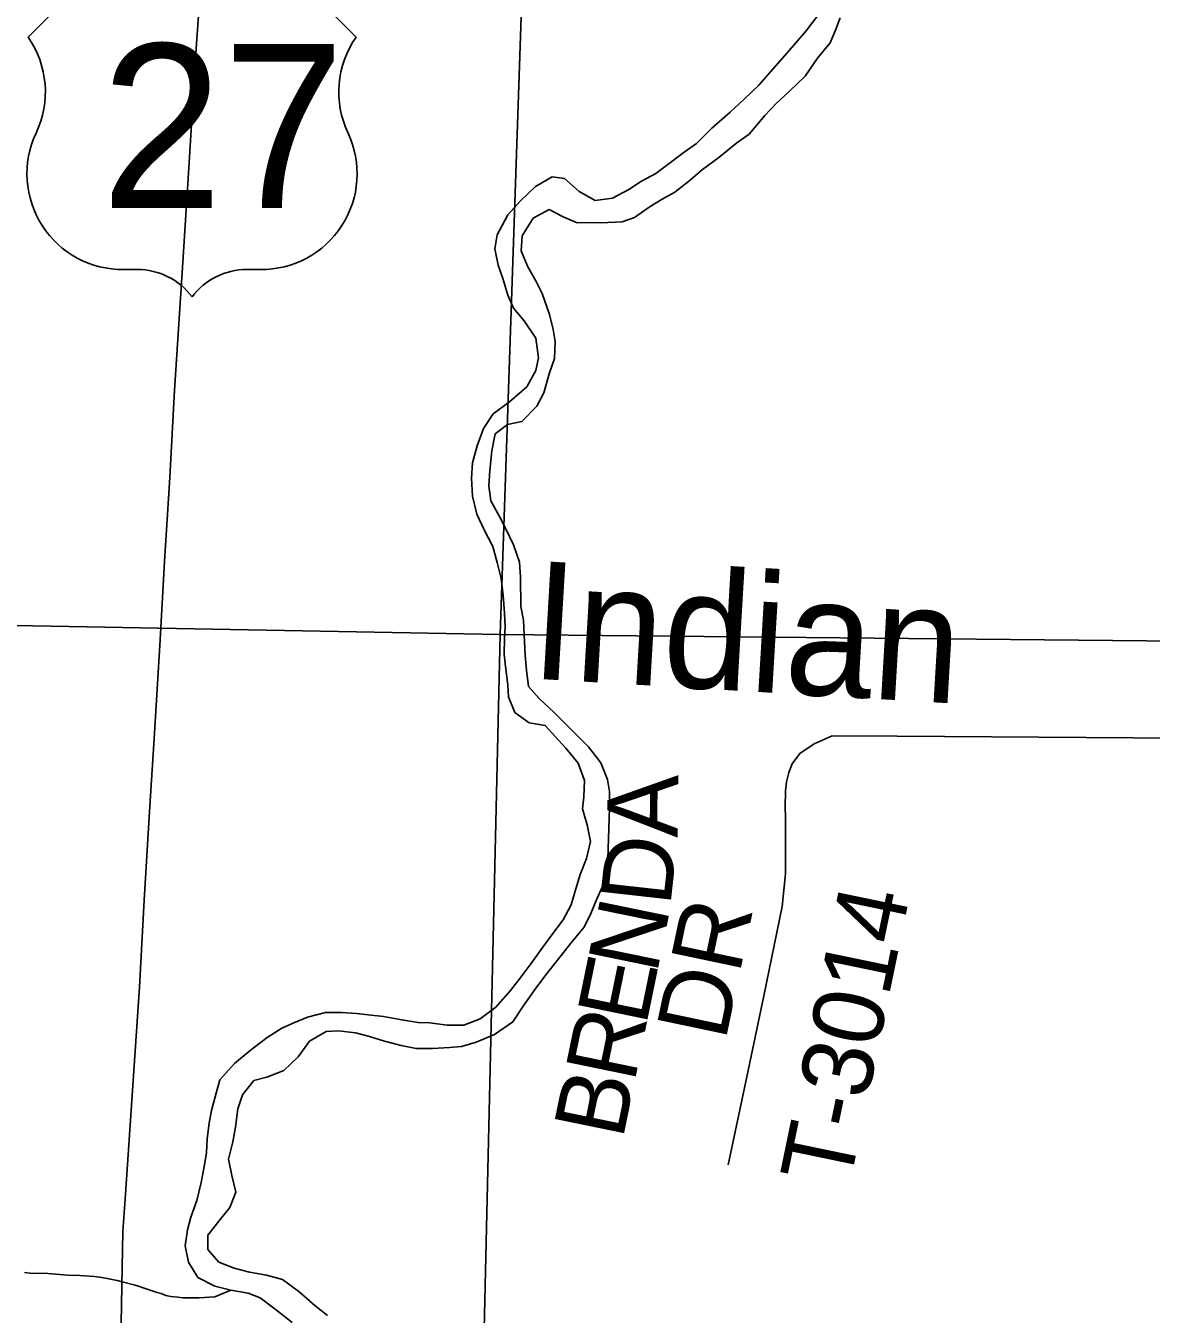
# Model space of a CAD drawing. Extents: x 0 to 34, y -2.3 to 22.
# Drawn here: x 5.006 to 5.911, y 18.814 to 19.85 of the extents above; entities that cross this region are included whole.
import ezdxf

# ---------------------------------------------------------------- set-up
doc = ezdxf.new("R2010")
doc.units = 0
for name, color, linetype in [('GM_X_Major_River', 7, 'Continuous'), ('GM_X_Minor_River', 7, 'Continuous'), ('GM_X_Minor_River_Text', 7, 'Continuous'), ('GM_X_Section', 7, 'Continuous'), ('GM_X_Township_Road', 7, 'Continuous'), ('GM_X_Township_Road_Text', 7, 'Continuous'), ('GM_X_US_Location', 7, 'Continuous'), ('GM_X_US_Route', 7, 'Continuous'), ('GM_X_US_Shield', 7, 'Continuous')]:
    doc.layers.add(name, color=color, linetype=linetype)

msp = doc.modelspace()

# ---------------------------------------------------------------- linework, layer by layer
at = {"layer": 'GM_X_Major_River'}
for p, q in [((5.6435, 19.859), (5.6333, 19.8456)), ((5.6569, 19.8462), (5.6605, 19.856)), ((5.6333, 19.8456), (5.6251, 19.8359)), ((5.6525, 19.8361), (5.6569, 19.8462)), ((5.6251, 19.8359), (5.6142, 19.8236)), ((5.6424, 19.8237), (5.6525, 19.8361)), ((5.6142, 19.8236), (5.6045, 19.8127)), ((5.6326, 19.8091), (5.6424, 19.8237)), ((5.6045, 19.8127), (5.5952, 19.8019)), ((5.6198, 19.7972), (5.6326, 19.8091)), ((5.5952, 19.8019), (5.5835, 19.7908)), ((5.6093, 19.7872), (5.6198, 19.7972)), ((5.5835, 19.7908), (5.5723, 19.7803)), ((5.6, 19.7775), (5.6093, 19.7872)), ((5.5723, 19.7803), (5.5576, 19.7674)), ((5.5875, 19.7626), (5.6, 19.7775)), ((5.5576, 19.7674), (5.5452, 19.7551)), ((5.5775, 19.7555), (5.5875, 19.7626)), ((5.5452, 19.7551), (5.5351, 19.7481)), ((5.5632, 19.7437), (5.5775, 19.7555)), ((5.5351, 19.7481), (5.522, 19.7381)), ((5.55, 19.7341), (5.5632, 19.7437)), ((5.5124, 19.731), (5.5008, 19.7248)), ((5.522, 19.7381), (5.5124, 19.731)), ((5.5388, 19.7244), (5.55, 19.7341)), ((5.4291, 19.7282), (5.4156, 19.7205)), ((5.4389, 19.7269), (5.4291, 19.7282)), ((5.4509, 19.7164), (5.4389, 19.7269)), ((5.5008, 19.7248), (5.4908, 19.7182)), ((5.5276, 19.7159), (5.5388, 19.7244)), ((5.4156, 19.7205), (5.4036, 19.709)), ((5.4636, 19.7093), (5.4509, 19.7164)), ((5.4777, 19.7112), (5.4636, 19.7093)), ((5.4908, 19.7182), (5.4777, 19.7112)), ((5.508, 19.7045), (5.5176, 19.7104)), ((5.5176, 19.7104), (5.5276, 19.7159)), ((5.4036, 19.709), (5.3935, 19.6978)), ((5.4139, 19.6951), (5.4266, 19.702)), ((5.4266, 19.702), (5.4379, 19.6961)), ((5.4953, 19.6957), (5.508, 19.7045)), ((5.3935, 19.6978), (5.3848, 19.6816)), ((5.4049, 19.6808), (5.4139, 19.6951)), ((5.4379, 19.6961), (5.4492, 19.6913)), ((5.4492, 19.6913), (5.4587, 19.6915)), ((5.4587, 19.6915), (5.4682, 19.6913)), ((5.4682, 19.6913), (5.4853, 19.6921)), ((5.4853, 19.6921), (5.4953, 19.6957)), ((5.3848, 19.6816), (5.383, 19.6703)), ((5.4043, 19.6687), (5.4049, 19.6808)), ((5.383, 19.6703), (5.3858, 19.6573)), ((5.4093, 19.6564), (5.4043, 19.6687)), ((5.3858, 19.6573), (5.3894, 19.6466)), ((5.4163, 19.6441), (5.4093, 19.6564)), ((5.3894, 19.6466), (5.3936, 19.6332)), ((5.421, 19.6345), (5.4163, 19.6441)), ((5.3936, 19.6332), (5.398, 19.6228)), ((5.4271, 19.6177), (5.421, 19.6345)), ((5.398, 19.6228), (5.4065, 19.6124)), ((5.4299, 19.6055), (5.4271, 19.6177)), ((5.4065, 19.6124), (5.4161, 19.5985)), ((5.4161, 19.5985), (5.418, 19.5829)), ((5.4316, 19.5959), (5.4299, 19.6055)), ((5.4309, 19.5823), (5.4316, 19.5959)), ((5.418, 19.5829), (5.4159, 19.5727)), ((5.4269, 19.5706), (5.4309, 19.5823)), ((5.4159, 19.5727), (5.4088, 19.5596)), ((5.4224, 19.5547), (5.4269, 19.5706)), ((5.4088, 19.5596), (5.3949, 19.5473)), ((5.3949, 19.5473), (5.3817, 19.5377)), ((5.4168, 19.5438), (5.4224, 19.5547)), ((5.3817, 19.5377), (5.3739, 19.5261)), ((5.4048, 19.5315), (5.4168, 19.5438)), ((5.3739, 19.5261), (5.3687, 19.5121)), ((5.3833, 19.5217), (5.3933, 19.5291)), ((5.3933, 19.5291), (5.4048, 19.5315)), ((5.3807, 19.5081), (5.3833, 19.5217)), ((5.3687, 19.5121), (5.365, 19.4985)), ((5.3789, 19.4922), (5.3807, 19.5081)), ((5.365, 19.4985), (5.3643, 19.486)), ((5.3643, 19.486), (5.3651, 19.4716)), ((5.3782, 19.48), (5.3789, 19.4922)), ((5.3799, 19.4678), (5.3782, 19.48)), ((5.3651, 19.4716), (5.3686, 19.457)), ((5.3868, 19.4552), (5.3799, 19.4678)), ((5.3686, 19.457), (5.3745, 19.4444)), ((5.392, 19.4452), (5.3868, 19.4552)), ((5.3745, 19.4444), (5.3814, 19.431)), ((5.3981, 19.4325), (5.392, 19.4452)), ((5.3814, 19.431), (5.3849, 19.4183)), ((5.4028, 19.4184), (5.3981, 19.4325)), ((5.3849, 19.4183), (5.3881, 19.4054)), ((5.4037, 19.4066), (5.4028, 19.4184)), ((5.3881, 19.4054), (5.3897, 19.3917)), ((5.4039, 19.383), (5.4037, 19.4066)), ((5.3897, 19.3917), (5.3909, 19.3776)), ((5.406, 19.3719), (5.4039, 19.383)), ((5.3909, 19.3776), (5.3914, 19.3665)), ((5.4065, 19.3602), (5.406, 19.3719)), ((5.3914, 19.3665), (5.3909, 19.3571)), ((5.4073, 19.3438), (5.4065, 19.3602)), ((5.3909, 19.3571), (5.3906, 19.3445)), ((5.3906, 19.3445), (5.3915, 19.3346)), ((5.4086, 19.3316), (5.4073, 19.3438)), ((5.3915, 19.3346), (5.3935, 19.3198)), ((5.4102, 19.3187), (5.4086, 19.3316)), ((5.3935, 19.3198), (5.394, 19.3103)), ((5.4187, 19.309), (5.4102, 19.3187)), ((5.394, 19.3103), (5.3991, 19.2976)), ((5.431, 19.2974), (5.4187, 19.309)), ((5.3991, 19.2976), (5.4107, 19.2894)), ((5.4583, 19.27), (5.431, 19.2974)), ((5.4107, 19.2894), (5.4236, 19.2872)), ((5.4236, 19.2872), (5.44, 19.269)), ((5.44, 19.269), (5.45, 19.2569)), ((5.4682, 19.2572), (5.4583, 19.27)), ((5.45, 19.2569), (5.4552, 19.2431)), ((5.4735, 19.2437), (5.4682, 19.2572)), ((5.4552, 19.2431), (5.4545, 19.2298)), ((5.4751, 19.2342), (5.4735, 19.2437)), ((5.4751, 19.2208), (5.4751, 19.2342)), ((5.4545, 19.2298), (5.4534, 19.2203)), ((5.4534, 19.2203), (5.4572, 19.2073)), ((5.4737, 19.1718), (5.4751, 19.2208)), ((5.4572, 19.2073), (5.4599, 19.1939)), ((5.4599, 19.1939), (5.4568, 19.1803)), ((5.4568, 19.1803), (5.4515, 19.1675)), ((5.4703, 19.1598), (5.4737, 19.1718)), ((5.4515, 19.1675), (5.4481, 19.1559)), ((5.4481, 19.1559), (5.4443, 19.143)), ((5.4646, 19.1466), (5.4703, 19.1598)), ((5.4443, 19.143), (5.4379, 19.1311)), ((5.4601, 19.1361), (5.4646, 19.1466)), ((5.4379, 19.1311), (5.4304, 19.121)), ((5.4548, 19.1252), (5.4601, 19.1361)), ((5.4304, 19.121), (5.4209, 19.108)), ((5.4442, 19.1122), (5.4548, 19.1252)), ((5.4335, 19.0985), (5.4442, 19.1122)), ((5.4209, 19.108), (5.4129, 19.0968)), ((5.4129, 19.0968), (5.403, 19.0838)), ((5.4252, 19.0881), (5.4335, 19.0985)), ((5.403, 19.0838), (5.3955, 19.0741)), ((5.4161, 19.0762), (5.4252, 19.0881)), ((5.3955, 19.0741), (5.3837, 19.0608)), ((5.4058, 19.0617), (5.4161, 19.0762)), ((5.3837, 19.0608), (5.3713, 19.0513)), ((5.3975, 19.049), (5.4058, 19.0617)), ((5.2215, 19.0481), (5.2119, 19.0438)), ((5.2323, 19.0527), (5.2215, 19.0481)), ((5.2468, 19.0564), (5.2323, 19.0527)), ((5.2597, 19.0564), (5.2468, 19.0564)), ((5.2719, 19.0557), (5.2597, 19.0564)), ((5.2813, 19.0547), (5.2719, 19.0557)), ((5.2935, 19.0532), (5.2813, 19.0547)), ((5.3082, 19.0505), (5.2935, 19.0532)), ((5.3214, 19.0485), (5.3082, 19.0505)), ((5.3309, 19.0483), (5.3214, 19.0485)), ((5.3446, 19.0463), (5.3309, 19.0483)), ((5.3713, 19.0513), (5.3582, 19.0463)), ((5.3827, 19.0388), (5.3975, 19.049)), ((5.2119, 19.0438), (5.1999, 19.0365)), ((5.234, 19.0336), (5.2475, 19.0412)), ((5.2475, 19.0412), (5.2574, 19.0417)), ((5.2574, 19.0417), (5.271, 19.0401)), ((5.271, 19.0401), (5.2823, 19.0371)), ((5.2823, 19.0371), (5.2944, 19.0334)), ((5.3582, 19.0463), (5.3446, 19.0463)), ((5.3681, 19.0327), (5.3827, 19.0388)), ((5.1999, 19.0365), (5.1863, 19.0259)), ((5.2249, 19.021), (5.234, 19.0336)), ((5.2944, 19.0334), (5.3076, 19.0299)), ((5.3076, 19.0299), (5.3197, 19.0277)), ((5.3197, 19.0277), (5.333, 19.0277)), ((5.333, 19.0277), (5.3467, 19.0284)), ((5.3467, 19.0284), (5.3562, 19.0293)), ((5.3562, 19.0293), (5.3681, 19.0327)), ((5.1863, 19.0259), (5.1738, 19.0156)), ((5.2135, 19.0099), (5.2249, 19.021)), ((5.1738, 19.0156), (5.162, 19.0023)), ((5.1997, 19.0046), (5.2135, 19.0099)), ((5.162, 19.0023), (5.1582, 18.9887)), ((5.1803, 18.9903), (5.1893, 19.0018)), ((5.1893, 19.0018), (5.1997, 19.0046)), ((5.1582, 18.9887), (5.1552, 18.9778)), ((5.1765, 18.979), (5.1803, 18.9903)), ((5.1552, 18.9778), (5.1534, 18.9679)), ((5.1746, 18.9643), (5.1765, 18.979)), ((5.1534, 18.9679), (5.1519, 18.9547)), ((5.1519, 18.9547), (5.1512, 18.944)), ((5.1723, 18.9525), (5.1746, 18.9643)), ((5.1512, 18.944), (5.1497, 18.9342)), ((5.1689, 18.9386), (5.1723, 18.9525)), ((5.1497, 18.9342), (5.147, 18.9198)), ((5.1715, 18.9256), (5.1689, 18.9386)), ((5.1749, 18.9122), (5.1715, 18.9256)), ((5.147, 18.9198), (5.1436, 18.9055)), ((5.1436, 18.9055), (5.1386, 18.8919)), ((5.17, 18.8997), (5.1749, 18.9122)), ((5.1621, 18.8901), (5.17, 18.8997)), ((5.136, 18.8817), (5.1341, 18.8689)), ((5.1386, 18.8919), (5.136, 18.8817)), ((5.1522, 18.8775), (5.1621, 18.8901)), ((5.1523, 18.866), (5.1522, 18.8775)), ((5.1341, 18.8689), (5.1368, 18.8559)), ((5.1611, 18.8559), (5.1523, 18.866)), ((5.1368, 18.8559), (5.1444, 18.8435)), ((5.1735, 18.851), (5.1611, 18.8559)), ((5.1859, 18.8479), (5.1735, 18.851)), ((5.1444, 18.8435), (5.1579, 18.8366)), ((5.1996, 18.8453), (5.1859, 18.8479)), ((5.2124, 18.8418), (5.1996, 18.8453)), ((5.2254, 18.8323), (5.2124, 18.8418)), ((5.1579, 18.8366), (5.1707, 18.8332)), ((5.1707, 18.8332), (5.1847, 18.8309)), ((5.1847, 18.8309), (5.1945, 18.8272)), ((5.2384, 18.8209), (5.2254, 18.8323)), ((5.1945, 18.8272), (5.2075, 18.8173)), ((5.2484, 18.813), (5.2384, 18.8209)), ((5.2075, 18.8173), (5.2201, 18.8074))]:
    msp.add_line(p, q, dxfattribs=at)
at = {"layer": 'GM_X_Minor_River'}
for p, q in [((5.0095, 18.8471), (5.005, 18.8476)), ((5.0236, 18.8467), (5.0095, 18.8471)), ((5.0399, 18.8454), (5.0236, 18.8467)), ((5.0494, 18.8452), (5.0399, 18.8454)), ((5.0611, 18.8444), (5.0494, 18.8452)), ((5.0672, 18.8435), (5.0611, 18.8444)), ((5.0713, 18.8426), (5.0672, 18.8435)), ((5.0793, 18.8412), (5.0713, 18.8426)), ((5.0834, 18.84), (5.0793, 18.8412)), ((5.094, 18.8374), (5.0834, 18.84)), ((5.0966, 18.8365), (5.094, 18.8374)), ((5.1011, 18.8349), (5.0966, 18.8365)), ((5.1117, 18.8315), (5.1011, 18.8349)), ((5.1147, 18.8307), (5.1117, 18.8315)), ((5.1185, 18.829), (5.1147, 18.8307)), ((5.1707, 18.8332), (5.158, 18.8279)), ((5.1226, 18.8282), (5.1185, 18.829)), ((5.1283, 18.8276), (5.1226, 18.8282)), ((5.1321, 18.8271), (5.1283, 18.8276)), ((5.1454, 18.8271), (5.1321, 18.8271)), ((5.158, 18.8279), (5.1454, 18.8271))]:
    msp.add_line(p, q, dxfattribs=at)
at = {"layer": 'GM_X_Section'}
for p, q in [((5.4223, 20.3866), (5.3873, 19.3604)), ((5.3873, 19.3604), (5.4223, 20.3866)), ((5.3873, 19.3604), (4.3717, 19.3789)), ((4.3717, 19.3789), (5.3873, 19.3604)), ((5.3873, 19.3604), (5.3638, 18.3497)), ((5.3638, 18.3497), (5.3873, 19.3604)), ((6.6178, 19.348), (5.3873, 19.3604)), ((5.3873, 19.3604), (6.6178, 19.348))]:
    msp.add_line(p, q, dxfattribs=at)
at = {"layer": 'GM_X_Township_Road'}
for p, q in [((5.6396, 19.2726), (5.6541, 19.279)), ((5.6541, 19.279), (5.7065, 19.2786)), ((5.7065, 19.2786), (6.0071, 19.2767)), ((5.6281, 19.2648), (5.6396, 19.2726)), ((5.6193, 19.2495), (5.622, 19.2565)), ((5.622, 19.2565), (5.6281, 19.2648)), ((5.6175, 19.2419), (5.6193, 19.2495)), ((5.6164, 19.2219), (5.6166, 19.2348)), ((5.6166, 19.2348), (5.6175, 19.2419)), ((5.6168, 19.2129), (5.6164, 19.2219)), ((5.6166, 19.204), (5.6168, 19.2129)), ((5.6166, 19.1679), (5.6166, 19.204)), ((5.614, 19.1416), (5.6166, 19.1679)), ((5.5993, 19.0699), (5.614, 19.1416)), ((5.5856, 19.0049), (5.5993, 19.0699)), ((5.5705, 18.9342), (5.5856, 19.0049))]:
    msp.add_line(p, q, dxfattribs=at)
at = {"layer": 'GM_X_US_Route'}
for p, q in [((5.1427, 19.8276), (5.1454, 19.8656)), ((5.1407, 19.7964), (5.1427, 19.8276)), ((5.1366, 19.7269), (5.1407, 19.7964)), ((5.1313, 19.6471), (5.1366, 19.7269)), ((5.1256, 19.5567), (5.1313, 19.6471)), ((5.1217, 19.4866), (5.1256, 19.5567)), ((5.1174, 19.4191), (5.1217, 19.4866)), ((5.1141, 19.356), (5.1174, 19.4191)), ((5.1092, 19.2768), (5.1141, 19.356)), ((5.1055, 19.218), (5.1092, 19.2768)), ((5.101, 19.1469), (5.1055, 19.218)), ((5.0973, 19.0768), (5.101, 19.1469)), ((5.0919, 18.9978), (5.0973, 19.0768)), ((5.0861, 18.9105), (5.0919, 18.9978)), ((5.0841, 18.8806), (5.0861, 18.9105)), ((5.0831, 18.8367), (5.0841, 18.8806)), ((5.0827, 18.8065), (5.0831, 18.8367))]:
    msp.add_line(p, q, dxfattribs=at)
at = {"layer": 'GM_X_US_Shield'}
for p, q in [((5.0627, 19.8955), (5.0078, 19.8406)), ((5.2715, 19.8406), (5.2165, 19.8955)), ((5.0847, 19.6538), (5.0957, 19.6538)), ((5.1836, 19.6538), (5.1946, 19.6538))]:
    msp.add_line(p, q, dxfattribs=at)
for centre, radius, start, end in [((4.9448, 19.7965), 0.0769, 334.5471, 35.0009), ((5.3345, 19.7965), 0.0769, 144.9991, 205.4529), ((5.0838, 19.7307), 0.0769, 154.8319, 270.6383), ((5.1954, 19.7307), 0.0769, 269.3617, 25.1681), ((5.0957, 19.5989), 0.0549, 36.8699, 90), ((5.1836, 19.5989), 0.0549, 90, 143.1301)]:
    msp.add_arc(centre, radius, start, end, dxfattribs=at)

# ---------------------------------------------------------------- texts
at = {"layer": 'GM_X_Minor_River_Text'}
msp.add_text('Indian', height=0.09469, rotation=356.6108, dxfattribs=at).set_placement((5.4107, 19.3251))
at = {"layer": 'GM_X_Township_Road_Text'}
for s, height, rotation, p in [('A', 0.0568, 89.2684, (5.53, 19.1969)), ('D', 0.0568, 83.6192, (5.524, 19.1411)), ('T-3014', 0.05682, 78.2794, (5.6678, 18.9151)), ('N', 0.0568, 78.3791, (5.5131, 19.0865)), ('DR', 0.05682, 78.1113, (5.5683, 19.0328)), ('E', 0.0568, 78.3802, (5.5045, 19.0449)), ('R', 0.0568, 78.3794, (5.4951, 18.9991)), ('B', 0.0568, 78.3793, (5.4857, 18.9534))]:
    msp.add_text(s, height=height, rotation=rotation, dxfattribs=at).set_placement(p)
at = {"layer": 'GM_X_US_Location'}
for s in ['/', '0']:
    msp.add_text(s, height=0.000189, dxfattribs=at).set_placement((5.1396, 19.7682))
msp.add_text('27', height=0.000189, rotation=0, dxfattribs=at).set_placement((5.1005, 19.7289))
at = {"layer": 'GM_X_US_Shield'}
msp.add_text('27', height=0.13184, dxfattribs=at).set_placement((5.0663, 19.7033))

doc.saveas('drawing.dxf')
